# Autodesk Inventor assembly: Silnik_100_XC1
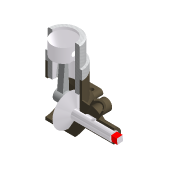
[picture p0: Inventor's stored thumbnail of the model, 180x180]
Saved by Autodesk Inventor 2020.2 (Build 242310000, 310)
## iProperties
Created: 2000-05
Part Number: Silnik_100_XC1
Document SubType Name: Assembly
Designer: F.Stasiak
Catalog Web Link: www.expertbooks.pl
Manager: www.cadconsulting.pl
Company: Fabian Stasiak CAD Consulting
Control State: 0
Master: False
Checked Out: False
Shininess: 0.0
Density: 0.0
Volumn: 0.0
Area: 0.0
PropertySet Name: Model Information
Author: F.Stasiak
Subject: Zbiór ćwiczeń. Autodesk Inventor 2020. Kurs Professional
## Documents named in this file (7)
- C:\2020_Kurs_Professional\R3 Dynamika\Silnik_100_XC1.iam
- C:\2020_Kurs_Professional\R3 Dynamika\Komponenty_dyn\Swożeń_XC15.ipt
- C:\2020_Kurs_Professional\R3 Dynamika\Komponenty_dyn\Tłok_XC15.ipt
- C:\2020_Kurs_Professional\R3 Dynamika\Komponenty_dyn\Korbowód_XC15.ipt
- C:\2020_Kurs_Professional\R3 Dynamika\Komponenty_dyn\Wałek_XC15.ipt
- C:\2020_Kurs_Professional\R3 Dynamika\Komponenty_dyn\Korpus_XC15.ipt
- C:\2020_Kurs_Professional\R3 Dynamika\Komponenty_dyn\Cylinder_XC15.ipt
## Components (6 placed, 6 different names)
1. Korpus
2. Cylinder
3. Korbowód
4. Wałek
5. Sworzeń
6. Tłok
